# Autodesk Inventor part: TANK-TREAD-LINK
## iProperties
Created: 2007-09
Part Number: TANK-TREAD-LINK
Material: ABS Plastic
Document SubType Name: Modeling
Density: 1.06 g/cm^3
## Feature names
1. Base1
